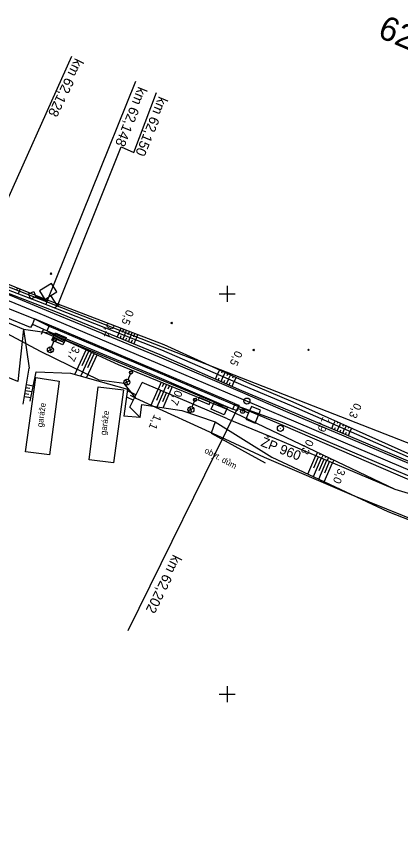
# Model space of a CAD drawing. Extents: x -805636 to -804553, y -1165340 to -1164656.
# Drawn here: x -805352.6 to -805256.7, y -1165035.6 to -1164830.7 of the extents above; entities that cross this region are included whole.
import ezdxf

# ---------------------------------------------------------------- set-up
doc = ezdxf.new("R2010")
doc.units = 0
for name, color, linetype in [('0381KM061-064P - Vrstva 1', 7, 'Continuous'), ('0381KM061-064P - Vrstva 13', 7, 'Continuous'), ('0381KM061-064P - Vrstva 14', 7, 'Continuous'), ('0381KM061-064P - Vrstva 16', 7, 'Continuous'), ('0381KM061-064P - Vrstva 17', 7, 'Continuous'), ('0381KM061-064P - Vrstva 23', 7, 'Continuous'), ('0381KM061-064P - Vrstva 25', 7, 'Continuous'), ('0381KM061-064P - Vrstva 4', 7, 'Continuous'), ('0381KM061-064P - Vrstva 48', 7, 'Continuous'), ('0381KM061-064P - Vrstva 49', 7, 'Continuous'), ('0381KM061-064P - Vrstva 7', 7, 'Continuous'), ('0381KM061-064P - Vrstva 8', 7, 'Continuous'), ('hran DP - hran DP', 7, 'Continuous'), ('krizky_1000 - Vrstva 1', 7, 'Continuous'), ('vyt_sit - stávající', 7, 'Continuous')]:
    doc.layers.add(name, color=color, linetype=linetype)

msp = doc.modelspace()

# ---------------------------------------------------------------- linework, layer by layer
at = {"layer": '0381KM061-064P - Vrstva 1'}
for points in [[(-805362.07, -1164898.64), (-805347.39, -1164904.64), (-805344.65, -1164905.78)], [(-805344.65, -1164905.78), (-805313.66, -1164918.88), (-805286.17, -1164930.55), (-805256.63, -1164943.09), (-805230.48, -1164954.2), (-805205.12, -1164965.01), (-805202.66, -1164966.06)]]:
    msp.add_lwpolyline(points, dxfattribs=at)
at = {"layer": '0381KM061-064P - Vrstva 13'}
msp.add_lwpolyline([(-805321.75, -1164930.89), (-805321.36, -1164927.66), (-805311.3, -1164929.13), (-805302.99, -1164931.92), (-805304.04, -1164934.8)], dxfattribs=at)
at = {"layer": '0381KM061-064P - Vrstva 14'}
for points in [[(-805348.61, -1164907.57), (-805344.97, -1164909.22), (-805344.37, -1164907.83), (-805348.12, -1164906.22)], [(-805298.03, -1164927.49), (-805318.81, -1164918.63), (-805344.37, -1164907.83)], [(-805344.97, -1164909.22), (-805319.37, -1164919.91), (-805298.61, -1164928.83), (-805298.03, -1164927.49)], [(-805298.03, -1164927.49), (-805297.09, -1164927.83), (-805297.56, -1164929.24), (-805298.61, -1164928.83)]]:
    msp.add_lwpolyline(points, dxfattribs=at)
at = {"layer": '0381KM061-064P - Vrstva 16'}
msp.add_lwpolyline([(-805366.38, -1164898.98), (-805348.12, -1164906.22), (-805348.61, -1164907.57), (-805349.09, -1164908.36), (-805367.46, -1164900.88), (-805366.38, -1164898.98)], dxfattribs=at)
at = {"layer": '0381KM061-064P - Vrstva 17'}
for points in [[(-805369.75, -1164914.7), (-805368.04, -1164901.63), (-805350.89, -1164908.84), (-805352.32, -1164921.91), (-805369.75, -1164914.7)], [(-805344.45, -1164909.76), (-805340.69, -1164911.4), (-805303.48, -1164926.91), (-805299.84, -1164928.84)]]:
    msp.add_lwpolyline(points, dxfattribs=at)
at = {"layer": '0381KM061-064P - Vrstva 23'}
for points in [[(-805344.35, -1164940.19), (-805350.35, -1164939.42), (-805347.83, -1164920.92), (-805341.94, -1164921.79), (-805344.35, -1164940.19)], [(-805334.52, -1164941.49), (-805332.2, -1164923.19), (-805325.94, -1164923.98), (-805328.43, -1164942.24), (-805334.52, -1164941.49)], [(-805304.04, -1164934.8), (-805290.52, -1164942.17)]]:
    msp.add_lwpolyline(points, dxfattribs=at)
for points in [[(-805304.5, -1164927.66), (-805304.24, -1164927.04), (-805306.99, -1164925.86), (-805307.26, -1164926.49)], [(-805300.76, -1164930.22), (-805304.05, -1164928.83), (-805303.22, -1164926.92), (-805299.93, -1164928.3)]]:
    msp.add_lwpolyline(points, close=True, dxfattribs=at)
at = {"layer": '0381KM061-064P - Vrstva 25'}
for p, q in [((-805343.87, -1164913.27), (-805343.29, -1164911.89)), ((-805342.87, -1164911.22), (-805343.53, -1164911.49)), ((-805342.74, -1164911.6), (-805343.35, -1164911.85)), ((-805343.5, -1164913.62), (-805344.84, -1164914.27)), ((-805343.92, -1164914.67), (-805344.41, -1164913.26)), ((-805324.77, -1164921.36), (-805324.19, -1164919.98)), ((-805323.78, -1164919.31), (-805324.43, -1164919.58)), ((-805323.65, -1164919.69), (-805324.26, -1164919.94)), ((-805324.4, -1164921.71), (-805325.74, -1164922.36)), ((-805324.83, -1164922.76), (-805325.31, -1164921.34)), ((-805308.78, -1164928.2), (-805308.19, -1164926.82)), ((-805307.78, -1164926.15), (-805308.43, -1164926.42)), ((-805307.64, -1164926.53), (-805308.26, -1164926.78)), ((-805308.41, -1164928.55), (-805309.75, -1164929.2)), ((-805308.83, -1164929.6), (-805309.31, -1164928.19))]:
    msp.add_line(p, q, dxfattribs=at)
for centre, radius in [((-805343.13, -1164911.52), 0.4), ((-805343.13, -1164911.52), 0.4), ((-805344.16, -1164913.96), 0.749), ((-805324.03, -1164919.61), 0.4), ((-805324.03, -1164919.61), 0.4), ((-805325.06, -1164922.05), 0.749), ((-805308.03, -1164926.45), 0.4), ((-805308.03, -1164926.45), 0.4), ((-805309.07, -1164928.89), 0.749)]:
    msp.add_circle(centre, radius, dxfattribs=at)
at = {"layer": '0381KM061-064P - Vrstva 4'}
for points in [[(-805364.7, -1164895.97), (-805343.19, -1164904.86), (-805317.03, -1164915.68), (-805296.75, -1164924.42), (-805284.83, -1164929.56), (-805254.7, -1164942.26), (-805226.16, -1164954.55), (-805203.52, -1164964.18), (-805187.57, -1164970.92)], [(-805364.7, -1164895.97), (-805342.91, -1164904.36), (-805316.81, -1164915.12), (-805296.46, -1164924.13), (-805284.52, -1164929.13), (-805254.45, -1164941.83), (-805225.92, -1164953.93), (-805203.38, -1164963.47), (-805187.4, -1164970.45)], [(-805348.12, -1164906.22), (-805344.46, -1164908.09), (-805318.48, -1164919.08), (-805298.17, -1164927.71), (-805286.08, -1164932.79)], [(-805298.17, -1164927.71), (-805285.87, -1164932.24)], [(-805286.08, -1164932.79), (-805257.4, -1164945.18)], [(-805285.87, -1164932.24), (-805257.21, -1164944.39)], [(-805257.4, -1164945.18), (-805227.5, -1164957.9), (-805205.55, -1164967.2), (-805161.7, -1164987.26), (-805121.4, -1165011.84), (-805082.08, -1165035.58)], [(-805257.21, -1164944.39), (-805227.21, -1164957.06), (-805205.17, -1164966.48), (-805161.59, -1164986.72), (-805120.84, -1165010.88), (-805082.03, -1165034.98)]]:
    msp.add_lwpolyline(points, dxfattribs=at)
at = {"layer": '0381KM061-064P - Vrstva 48'}
for p, q in [((-805352.38, -1164898.48), (-805352.62, -1164899.09)), ((-805351.69, -1164898.76), (-805352.17, -1164899.97)), ((-805327.03, -1164909.84), (-805326.53, -1164908.55)), ((-805327.08, -1164909.82), (-805327.46, -1164910.73)), ((-805326.54, -1164910.46), (-805326.77, -1164911.02)), ((-805326.13, -1164909.59), (-805325.83, -1164908.82)), ((-805325.69, -1164910.37), (-805326.07, -1164911.3)), ((-805325.63, -1164910.39), (-805325.13, -1164909.09)), ((-805324.73, -1164910.14), (-805324.43, -1164909.36)), ((-805324.24, -1164910.94), (-805323.73, -1164909.62)), ((-805323.34, -1164910.68), (-805323.04, -1164909.89)), ((-805322.84, -1164911.49), (-805322.34, -1164910.16)), ((-805325.14, -1164911.02), (-805325.38, -1164911.59)), ((-805324.29, -1164910.92), (-805324.69, -1164911.88)), ((-805323.75, -1164911.58), (-805323.99, -1164912.16)), ((-805322.9, -1164911.47), (-805323.3, -1164912.45)), ((-805338.05, -1164920.13), (-805335.23, -1164913.99)), ((-805336.59, -1164920.54), (-805333.87, -1164914.62)), ((-805336.21, -1164917.92), (-805334.55, -1164914.3)), ((-805335.12, -1164920.94), (-805332.51, -1164915.25)), ((-805334.79, -1164918.42), (-805333.19, -1164914.93)), ((-805302.93, -1164921.26), (-805302.4, -1164920.06)), ((-805301.91, -1164918.97), (-805302.4, -1164920.06)), ((-805301.56, -1164921.87), (-805301.02, -1164920.66)), ((-805301.23, -1164919.28), (-805301.47, -1164919.82)), ((-805300.54, -1164919.59), (-805301.03, -1164920.66)), ((-805299.86, -1164919.9), (-805300.1, -1164920.43)), ((-805299.18, -1164920.21), (-805299.65, -1164921.25)), ((-805298.49, -1164920.52), (-805298.73, -1164921.03)), ((-805297.81, -1164920.83), (-805298.27, -1164921.85)), ((-805348.46, -1164923.02), (-805350.15, -1164922.74)), ((-805316.54, -1164922.03), (-805317.26, -1164923.8)), ((-805315.84, -1164922.32), (-805316.21, -1164923.21)), ((-805315.15, -1164922.6), (-805315.88, -1164924.4)), ((-805314.45, -1164922.88), (-805314.82, -1164923.79)), ((-805302.24, -1164921.57), (-805301.98, -1164920.96)), ((-805300.87, -1164922.17), (-805300.6, -1164921.56)), ((-805300.19, -1164922.48), (-805299.64, -1164921.25)), ((-805299.5, -1164922.78), (-805299.23, -1164922.17)), ((-805298.81, -1164923.08), (-805298.27, -1164921.85)), ((-805349.55, -1164925.11), (-805350.5, -1164924.96)), ((-805348.76, -1164924.48), (-805350.38, -1164924.22)), ((-805349.27, -1164923.64), (-805350.26, -1164923.48)), ((-805324.95, -1164924.17), (-805322.77, -1164925.24)), ((-805319.05, -1164928), (-805317.25, -1164923.81)), ((-805317.59, -1164926.51), (-805316.56, -1164924.1)), ((-805317.51, -1164928.22), (-805315.87, -1164924.4)), ((-805316.12, -1164926.88), (-805315.18, -1164924.7)), ((-805315.97, -1164928.45), (-805314.49, -1164924.99)), ((-805313.76, -1164923.17), (-805314.5, -1164924.99)), ((-805349.06, -1164925.95), (-805350.62, -1164925.69)), ((-805325.14, -1164925.67), (-805323.4, -1164926.53)), ((-805324.26, -1164925.3), (-805323.09, -1164925.89)), ((-805273.91, -1164933.61), (-805273.44, -1164932.5)), ((-805273.06, -1164931.69), (-805273.43, -1164932.51)), ((-805272.38, -1164932), (-805272.56, -1164932.4)), ((-805272.52, -1164934.2), (-805272.06, -1164933.1)), ((-805271.7, -1164932.3), (-805272.05, -1164933.11)), ((-805271.01, -1164932.61), (-805271.19, -1164933.01)), ((-805270.33, -1164932.92), (-805270.68, -1164933.71)), ((-805273.21, -1164933.9), (-805272.98, -1164933.35)), ((-805271.83, -1164934.49), (-805271.6, -1164933.95)), ((-805271.14, -1164934.78), (-805270.69, -1164933.7)), ((-805270.45, -1164935.07), (-805270.23, -1164934.54)), ((-805269.64, -1164933.23), (-805269.82, -1164933.62)), ((-805269.76, -1164935.36), (-805269.31, -1164934.31)), ((-805268.96, -1164933.53), (-805269.31, -1164934.31)), ((-805279.84, -1164945.01), (-805277.88, -1164940.4)), ((-805278.48, -1164945.65), (-805276.5, -1164940.98)), ((-805278.37, -1164943.48), (-805277.19, -1164940.69)), ((-805277.44, -1164939.56), (-805277.85, -1164940.41)), ((-805277.01, -1164944.09), (-805275.81, -1164941.28)), ((-805276.76, -1164939.88), (-805276.96, -1164940.29)), ((-805276.09, -1164940.21), (-805276.46, -1164941)), ((-805275.41, -1164940.53), (-805275.59, -1164940.91)), ((-805274.73, -1164940.85), (-805275.08, -1164941.58)), ((-805274.06, -1164941.18), (-805274.22, -1164941.53)), ((-805277.12, -1164946.29), (-805275.12, -1164941.57)), ((-805275.77, -1164946.92), (-805273.74, -1164942.16)), ((-805275.64, -1164944.71), (-805274.43, -1164941.86)), ((-805273.38, -1164941.5), (-805273.7, -1164942.17))]:
    msp.add_line(p, q, dxfattribs=at)
at = {"layer": '0381KM061-064P - Vrstva 49'}
for p, q in [((-805343.83, -1164895.11), (-805344.18, -1164894.75)), ((-805343.83, -1164894.75), (-805344.18, -1164895.11)), ((-805313.7, -1164907.45), (-805314.05, -1164907.1)), ((-805313.7, -1164907.1), (-805314.05, -1164907.45)), ((-805293.23, -1164914.18), (-805293.58, -1164913.83)), ((-805293.23, -1164913.83), (-805293.58, -1164914.18)), ((-805279.54, -1164914.16), (-805279.9, -1164913.81)), ((-805279.54, -1164913.81), (-805279.9, -1164914.16))]:
    msp.add_line(p, q, dxfattribs=at)
for points in [[(-805364.02, -1164893.8), (-805346.07, -1164901.02), (-805315.87, -1164912.66), (-805295.19, -1164922.01)], [(-805366.61, -1164894.35), (-805364.7, -1164895.97), (-805342.91, -1164904.36), (-805316.81, -1164915.12), (-805296.46, -1164924.13)], [(-805364.49, -1164895.2), (-805347.1, -1164901.93), (-805316.44, -1164914.01), (-805295.94, -1164922.85)], [(-805350.89, -1164908.84), (-805349.46, -1164918.54)], [(-805350.89, -1164908.84), (-805344.45, -1164909.76), (-805327.24, -1164917.67), (-805299.84, -1164928.84), (-805258.14, -1164948.79)], [(-805350.92, -1164927.51), (-805349.46, -1164918.54)], [(-805349.24, -1164926.82), (-805347.72, -1164919.48), (-805339.1, -1164919.84), (-805324.89, -1164923.77)], [(-805321.75, -1164930.89), (-805324.29, -1164928.33), (-805321.22, -1164922.1)], [(-805299.97, -1164931.23), (-805321.22, -1164922.1)], [(-805295.94, -1164922.85), (-805284.04, -1164927.86), (-805253.46, -1164941.25), (-805223.68, -1164953.23)], [(-805295.19, -1164922.01), (-805283.65, -1164926.95), (-805253.5, -1164940.46), (-805223.68, -1164953.23)], [(-805324.89, -1164923.77), (-805325.79, -1164930.57)], [(-805296.46, -1164924.13), (-805284.52, -1164929.13), (-805254.45, -1164941.83), (-805225.92, -1164953.93)], [(-805321.75, -1164930.89), (-805321.36, -1164927.66), (-805311.3, -1164929.13), (-805302.99, -1164931.92)], [(-805321.75, -1164930.89), (-805325.79, -1164930.57)], [(-805302.99, -1164931.92), (-805288.85, -1164940.8), (-805259.86, -1164954.37)], [(-805299.97, -1164931.23), (-805286.39, -1164936.78), (-805258.14, -1164948.79)], [(-805258.14, -1164948.79), (-805227.5, -1164957.9)], [(-805259.86, -1164954.37), (-805233.78, -1164964.57)]]:
    msp.add_lwpolyline(points, dxfattribs=at)
at = {"layer": '0381KM061-064P - Vrstva 7'}
for p, q in [((-805343.05, -1164903.36), (-805341.79, -1164902.55)), ((-805297.43, -1164928.54), (-805324.84, -1164984.17)), ((-805297.14, -1164927.85), (-805297.72, -1164929.23)), ((-805296.2, -1164929.3), (-805296.11, -1164929.34))]:
    msp.add_line(p, q, dxfattribs=at)
for points in [[(-805342.42, -1164902.96), (-805326.45, -1164863.29), (-805323.31, -1164864.66), (-805317.63, -1164849.64)], [(-805342.42, -1164902.96), (-805344.04, -1164900.43), (-805342.56, -1164899.49), (-805343.91, -1164897.38), (-805346.86, -1164899.27), (-805345.51, -1164901.37), (-805344.04, -1164900.43)], [(-805297.43, -1164928.54), (-805294.67, -1164929.71), (-805295.35, -1164931.32), (-805293.05, -1164932.3), (-805291.68, -1164929.08), (-805293.98, -1164928.1), (-805294.67, -1164929.71)]]:
    msp.add_lwpolyline(points, dxfattribs=at)
for centre, radius in [((-805295.08, -1164926.77), 0.75), ((-805296.16, -1164929.32), 0.5)]:
    msp.add_circle(centre, radius, dxfattribs=at)
at = {"layer": '0381KM061-064P - Vrstva 8'}
for p, q in [((-805363.02, -1164894.54), (-805338.8, -1164840.62)), ((-805344.97, -1164901.83), (-805322.86, -1164846.82)), ((-805345.25, -1164902.52), (-805344.69, -1164901.13)), ((-805345.86, -1164908.78), (-805346.45, -1164910.16)), ((-805343.41, -1164911.01), (-805342.5, -1164910.64)), ((-805343.37, -1164910.58), (-805342.99, -1164910.43)), ((-805342.92, -1164911.21), (-805342.01, -1164910.84)), ((-805342.44, -1164911.42), (-805341.52, -1164911.05)), ((-805341.95, -1164911.63), (-805341.03, -1164911.26)), ((-805341.46, -1164911.83), (-805340.55, -1164911.46)), ((-805340.97, -1164912.04), (-805340.68, -1164911.92))]:
    msp.add_line(p, q, dxfattribs=at)
for points in [[(-805344.97, -1164901.83), (-805347.76, -1164900.72), (-805349.06, -1164901.28), (-805349.62, -1164899.98), (-805348.32, -1164899.42), (-805347.76, -1164900.72)], [(-805343.39, -1164910.63), (-805346.15, -1164909.47)], [(-805343, -1164909.72), (-805340.24, -1164910.88), (-805341.02, -1164912.73), (-805343.78, -1164911.56), (-805343, -1164909.72)]]:
    msp.add_lwpolyline(points, dxfattribs=at)
msp.add_lwpolyline([(-805343.26, -1164910.32), (-805340.49, -1164911.48), (-805340.76, -1164912.13), (-805343.53, -1164910.96)], close=True, dxfattribs=at)
at = {"layer": 'hran DP - hran DP'}
for p, q in [((-805367.78, -1164893.1), (-805249.75, -1164939.24)), ((-805346.65, -1164914.36), (-805367.9, -1164903.11)), ((-805332.02, -1164921.55), (-805346.65, -1164914.36)), ((-805325.7, -1164922.37), (-805332.02, -1164921.55)), ((-805322.74, -1164926.15), (-805325.7, -1164922.37)), ((-805300.55, -1164936.27), (-805322.74, -1164926.15)), ((-805290.72, -1164940.83), (-805300.55, -1164936.27)), ((-805268.35, -1164950.48), (-805290.72, -1164940.83)), ((-805235.86, -1164963.58), (-805268.35, -1164950.48))]:
    msp.add_line(p, q, dxfattribs=at)
at = {"layer": 'krizky_1000 - Vrstva 1'}
for points in [[(-805300, -1164898), (-805300, -1164902)], [(-805302, -1164900), (-805298, -1164900)], [(-805300, -1164998), (-805300, -1165002)], [(-805302, -1165000), (-805298, -1165000)]]:
    msp.add_lwpolyline(points, dxfattribs=at)
at = {"layer": 'vyt_sit - stávající'}
msp.add_line((-805286.76, -1164933.55), (-805286.68, -1164933.61), dxfattribs=at)
msp.add_circle((-805286.72, -1164933.58), 0.756, dxfattribs=at)

# ---------------------------------------------------------------- texts
at = {"layer": '0381KM061-064P - Vrstva 23'}
for s, rotation, p in [('garáže', 82.2322, (-805346.1, -1164933.37)), ('garáže', 82.7783, (-805330.26, -1164935.34)), (' obyt. dům', 331.3934, (-805306.33, -1164939.31))]:
    msp.add_text(s, height=1.5, rotation=rotation, dxfattribs=at).set_placement(p)
at = {"layer": '0381KM061-064P - Vrstva 48'}
for s, rotation, p in [('0,5', 248.495, (-805325.1, -1164903.79)), ('0,4', 247.5875, (-805329.86, -1164906.99)), ('3,7', 245.3182, (-805338.51, -1164912.91)), ('0,5', 245.6505, (-805297.92, -1164914.02)), ('0,7', 247.8034, (-805312.93, -1164923.87)), ('0,3', 245.8554, (-805268.17, -1164927.09)), ('1,1', 246.7728, (-805318.19, -1164929.95)), ('1,9', 247.0941, (-805276.08, -1164930.53)), ('0,3', 244.4427, (-805280.1, -1164936.16)), ('3,0', 246.9723, (-805272.24, -1164943.45))]:
    msp.add_text(s, height=2, rotation=rotation, dxfattribs=at).set_placement(p)
at = {"layer": '0381KM061-064P - Vrstva 7'}
for s, height, rotation, p in [('62,2', 6, 337.0034, (-805262.71, -1164835.71)), ('km 62,150', 2.5, 247.6272, (-805317.06, -1164850.49)), ('km 62,202', 2.5, 243.7716, (-805313.5, -1164964.97))]:
    msp.add_text(s, height=height, rotation=rotation, dxfattribs=at).set_placement(p)
at = {"layer": '0381KM061-064P - Vrstva 8'}
for s, rotation, p in [('km 62,128', 244.0036, (-805337.99, -1164840.93)), ('km 62,148', 248.1034, (-805322.21, -1164848.06))]:
    msp.add_text(s, height=2.5, rotation=rotation, dxfattribs=at).set_placement(p)
at = {"layer": 'vyt_sit - stávající'}
msp.add_text('ŽP 960', height=2.4, rotation=338.5611, dxfattribs=at).set_placement((-805291.82, -1164937.92))

doc.saveas('drawing.dxf')
